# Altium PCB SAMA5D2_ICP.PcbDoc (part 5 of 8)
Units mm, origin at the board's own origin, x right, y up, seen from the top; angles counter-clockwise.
Board outline 150 x 100 mm, 6 copper layers (L1 - TOP, L2 - GND, L3 - SIG, L4 - SIG, L5 - VCC, L6 - BOT), stack 1.512 mm thick; 708 components, 597 nets, 2710 pads, 1437 vias.
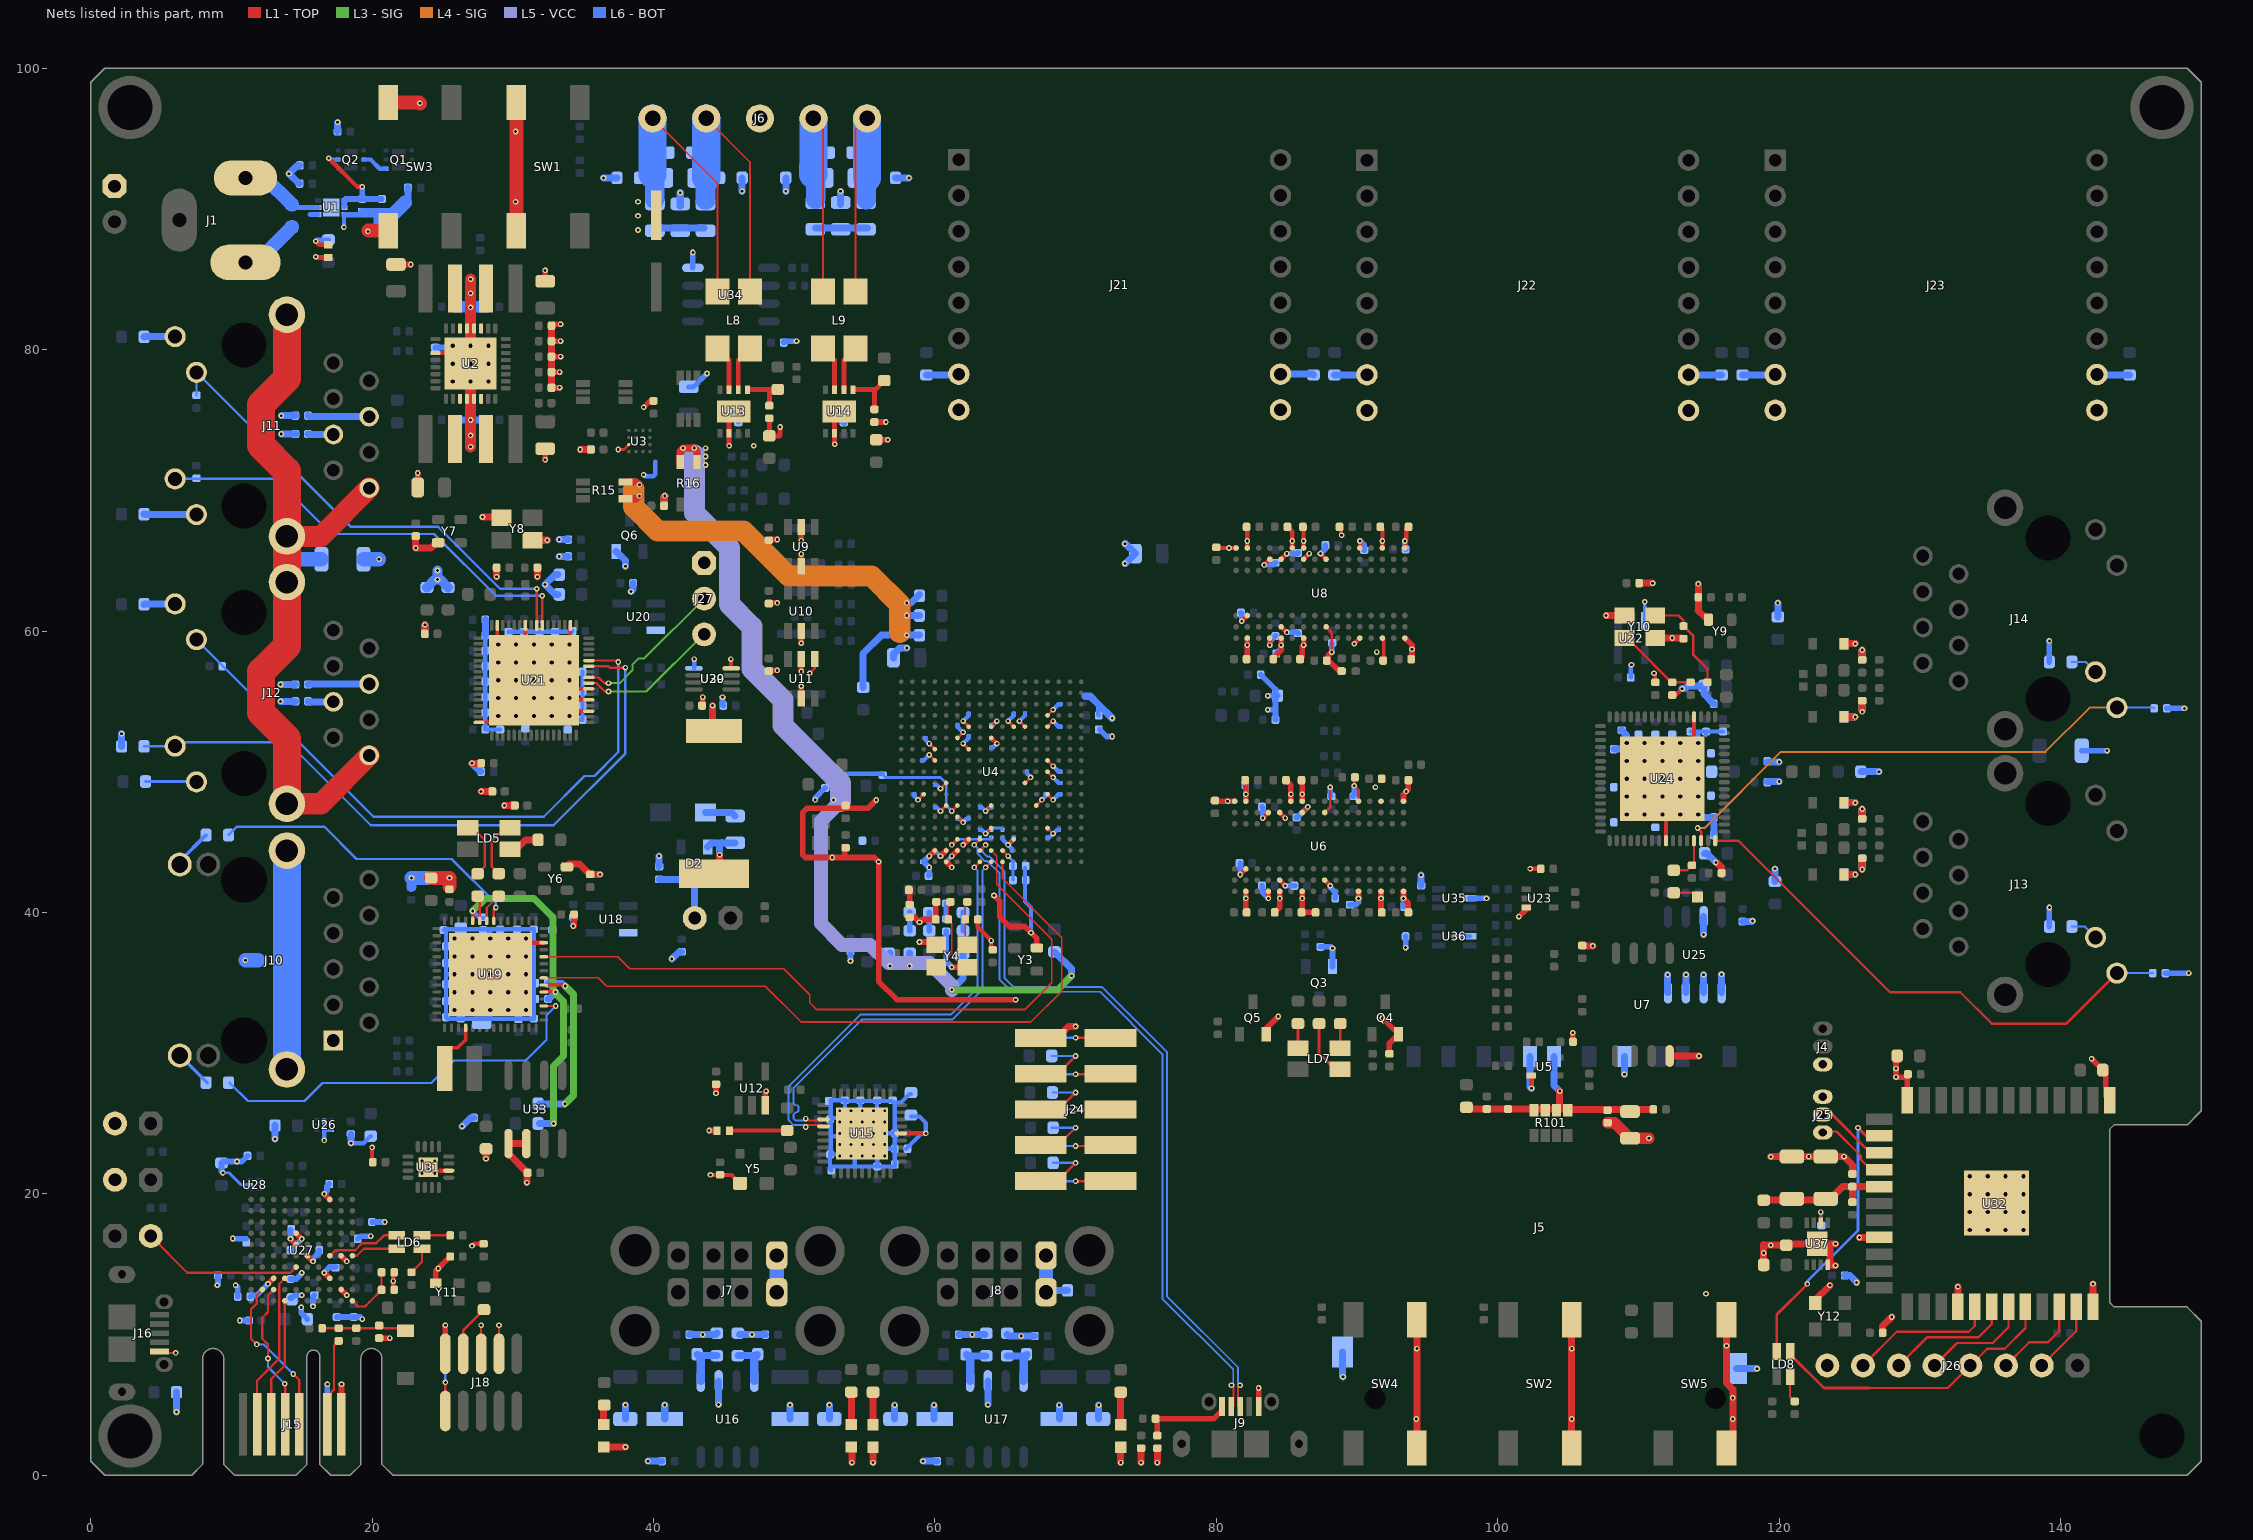
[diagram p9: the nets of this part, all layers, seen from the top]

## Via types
v1: diameter 0.4, hole 0.2, L1 - TOP to L6 - BOT, tented both sides, 1312 vias
v2: diameter 0.55, hole 0.3, L1 - TOP to L6 - BOT, 84 vias
v3: diameter 0.4, hole 0.2, L1 - TOP to L6 - BOT, tented top, 25 vias
v4: diameter 0.55, hole 0.3, L1 - TOP to L6 - BOT, tented bottom, 16 vias

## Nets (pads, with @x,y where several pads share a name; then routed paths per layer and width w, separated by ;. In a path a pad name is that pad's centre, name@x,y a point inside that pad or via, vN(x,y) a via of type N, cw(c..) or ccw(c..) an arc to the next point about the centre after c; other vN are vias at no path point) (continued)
GND: C1.1 C2.1 C3.1 C4.1 C5.2 C6.1 C7.1 C8.1 C9.1 C10.1 C11.1 C12.2 C13.1 C14.2 C15.1 C16.2 C17.1 C18.2 C19.1 C20.1 C21.1 C22.1 C23.1 C24.1 C26.1 C27.1 C28.1 C29.1 C30.1 C31.1 C32.1 C33.1 C34.1 C35.1 C36.1 C37.1 C38.1 C39.1 C40.1 C41.1 C42.1 C43.1 C44.1 C45.1 C46.1 C47.1 C48.1 C49.1 C50.1 C51.1 C52.1 C53.1 C54.1 C55.1 C56.1 C57.1 C58.1 C59.1 C60.1 C61.1 C62.1 C63.1 C64.1 C65.1 C66.1 C67.1 C68.2 C70.1 C72.1 C73.1 C75.1 C76.1 C77.1 C78.1 C79.1 C80.1 C81.1 C82.1 C83.1 C84.1 C85.1 C86.1 C87.1 C88.1 C89.1 C90.1 C91.1 C92.1 C93.1 C94.1 C95.1 C96.1 C97.1 C98.1 C99.1 C100.1 C101.1 C102.1 C103.1 C104.1 C105.1 C106.1 C107.1 C108.1 C109.1 C110.1 C111.1 C112.1 C113.1 C114.1 C115.1 C116.1 C117.1 C118.1 C119.1 C120.1 C121.1 C122.1 C123.1 C124.1 C125.1 C126.1 C127.1 C128.1 C129.1 C130.1 C131.1 C132.1 C133.1 C134.1 C135.1 C136.2 C137.2 C138.2 C139.2 C142.1 C143.1 C144.2 C145.2 C146.1 C147.1 C148.1 C149.1 C150.1 C151.1 C152.1 C153.1 C154.1 C155.1 C156.1 C157.1 C158.1 C159.1 C160.1 C161.1 C162.1 C163.1 C164.1 C165.1 C166.1 C167.2 C168.1 C169.1 C170.1 C171.1 C172.1 C173.1 C174.1 C175.1 C176.1 C177.1 C178.1 C179.1 C180.1 C181.1 C182.1 C183.1 C184.1 C185.1 C186.1 C187.1 C188.1 C189.1 C190.1 C191.1 C192.1 C193.1 C194.1 C195.1 C196.1 C197.1 C198.1 C199.1 C200.1 C201.1 C202.1 C203.1 C204.1 C205.1 C206.1 C207.1 C208.1 C209.1 C210.1 C211.1 C212.1 C213.2 C214.2 C215.2 C216.2 C217.1 C218.1 C219.1 C220.1 C221.1 C222.1 C223.1 C224.1 C225.1 C226.1 C227.1 C228.1 C229.1 C230.1 C231.1 C232.1 C233.1 C234.1 C235.1 C236.1 C237.1 C238.1 C239.1 C240.1 C241.1 C242.1 C244.1 C245.1 C246.1 C247.1 C248.1 C249.1 C250.1 C251.1 C252.1 C253.1 C254.1 C255.1 C256.1 C257.1 C258.1 C259.1 C260.1 C261.1 C262.1 C263.1 C264.1 C265.1 C266.1 C267.1 C268.1 C269.1 C270.1 C271.1 C272.1 C273.1 C274.1 C275.1 C276.1 C277.1 C278.2 C279.2 C280.1 C281.1 C282.1 C283.1 C284.1 C285.1 C286.1 C287.1 C288.1 C289.1 C290.2 C291.1 C292.1 C293.1 C294.1 C295.1 C296.1 C297.1 C298.1 C299.1 C300.2 C301.2 C302.1 C303.2 C304.1 C305.1 D3.2 D4.2 D11.1 D12.1 D13.1 D14.1 D15.1 D16.1 D17.1 D18.1 FB14.1 FB21.1 FB26.2 J1.2 J3.1 J4.3 J5.3 J5.6 J5.12 J6.3 J7.4 J7.8 J8.4 J8.8 J9.5 J10.1 J15.2 J15.3 J16.5 J18.3 J18.5 J18.9 J19.2 J20.2 J21.8 J21.9 J22.8 J22.9 J23.8 J23.9 J24.10 J25.3 J26.8 J27.1 LD1.2 LD2.2 LD3.2 LD4.2 Q3.2 Q4.2 Q5.2 Q6.2 R5.1 R8.1 R10.1 R11.2 R12.1 R13.2 R22.1 R26.1 R64.1 R66.2 R67.1 R76.1 R77.1 R79.2 R82.1 R85.1 R87.1 R92.1 R95.1 R111.1 R112.2 R120.2 R121.2 R122.2 R123.2 R129.1 R133.2 R136.1 R139.1 R149.1 R155.2 R157.2 R162.1 R164.1 R174.2 R175.1 R180.2 R181.2 R198.1 R206.1 R208.1 R216.1 R242.1 R243.1 R248.2 R259.2 R261.1 R262.1 R266.2 R267.2 R268.2 R271.1 SW1.3 SW1.4 SW2.3 SW2.4 SW3.3 SW3.4 SW4.3 SW4.4 SW5.3 SW5.4 U1.2 U1.6 U2.3 U2.12 U2.13 U2.28 U2.29 U2.33 U3.B4 U4.D14 U4.E7 U4.E9 U4.E11 U4.E12 U4.E14 U4.F6 U4.F9 U4.G4 U4.G7 U4.H4 U4.H14 U4.J14 U4.K5 U4.K12 U4.L3 U4.L14 U4.M5 U4.M9 U4.M13 U4.N6 U4.P14 U4.R7 U4.R11 U4.T4 U4.T5 U4.T6 U4.U5 U5.3 U6.A9 U6.B1 U6.B3 U6.B9 U6.D1 U6.D8 U6.E1 U6.E2 U6.E8 U6.F9 U6.G1 U6.G8 U6.G9 U6.J2 U6.J8 U6.M1 U6.M9 U6.P1 U6.P9 U6.T1 U6.T9 U7.4 U8.A9 U8.B1 U8.B3 U8.B9 U8.D1 U8.D8 U8.E1 U8.E2 U8.E8 U8.F9 U8.G1 U8.G8 U8.G9 U8.J2 U8.J8 U8.M1 U8.M9 U8.P1 U8.P9 U8.T1 U8.T9 U9.2 U9.5 U10.2 U11.2 U11.4 U11.5 U12.3 U13.2 U13.9 U14.2 U14.9 U15.37 U16.6 U17.6 U18.3 U19.40 U19.57 U20.3 U21.16 U21.35 U21.37 U21.39 U21.50 U21.58 U21.63 U21.65 U22.3 U23.3 U24.4 U24.41 U24.65 U25.1 U25.2 U25.3 U25.4 U25.7 U26.3 U26.7 U27.B2 U27.C3 U27.E2 U27.E5 U27.F6 U27.G6 U27.K3 U28.5 U29.4 U30.4 U31.6 U31.17 U32.1 U32.13 U32.21 U32.28 U32.36 U32.37 U33.5 U33.6 U34.4 U35.2 U36.2 U37.4 U37.9 Y3.2 Y4.2 Y4.4 Y5.2 Y6.2 Y7.2 Y8.2 Y8.4 Y9.2 Y10.2 Y10.4 Y11.2 Y12.2 | length 656.8
  L1 - TOP w0.15: J16.5@4.85,8.7 v1(6.05,8.7) ; U31.17@24,22.5 U31.17@24.25,22.25 ; J18.5@27.75,8.632 v1(27.75,10.664) ; J18.3@29.02,8.632 v1(29.02,10.664)
  L1 - TOP w0.2: v1(37.5,72.9) 37.9,72.9 U3.B4@38.25,73.25 ; v1(51.1,57) 51.125,57 51.45,57.325 U11.4@51.45,58 ; v1(58.8,48) U4.L3@59.2,48.4 ; v1(59.6,51.2) U4.H4@60,50.8 ; v1(59.6,52) U4.G4@60,51.6 ; v1(60.4,47.2) U4.M5@60.8,47.6 ; v1(60.4,48.8) U4.K5@60.8,49.2 ; U4.N6@61.6,46.8 v1(62,46.4) ; U4.F6@61.6,52.4 v1(62,52.8) ; v1(62,52) U4.G7@62.4,51.6 ; v1(62,53.6) U4.E7@62.4,53.2 ; v1(63.6,47.2) U4.M9@64,47.6 ; U4.E9@64,53.2 v1(64.4,53.6) ; v1(65.2,44.8) U4.R11@65.6,45.2 ; v1(65.2,53.6) U4.E11@65.6,53.2 ; v1(66,53.6) U4.E12@66.4,53.2 ; U4.K12@66.4,49.2 v1(66.8,49.6) ; U4.M13@67.2,47.6 v1(67.6,48) ; U4.P14@68,46 v1(68.4,45.6) ; U4.L14@68,48.4 v1(68.4,48) ; U4.J14@68,50 v1(68.4,49.6) ; U4.H14@68,50.8 v1(68.4,50.4) ; U4.E14@68,53.2 v1(68.4,53.6) ; U4.D14@68,54 v1(68.4,54.4) ; U6.J8@87.7,47.1 88.1,47.5 v1(88.1,48.9) ; U8.J2@87.8,60.3 88.2,59.9 v1(88.2,58.5) ; R85.1@89.85,49.6 89.8,49.55 v1(89.8,49) 90.1,48.7 U6.M9@90.1,47.9 ; U8.P1@91.8,59.5 U8.P1@91.85,59.45 ; U32.1@143.3,26.855 U32.1@143.5,26.655
  L1 - TOP w0.25: U21.16@27.6,53.5 U21.65@28.5,53.5 ; U21.65@28.9,59.1 U21.63@28.9,60.4 ; U21.65@30.9,57.1 U21.58@30.9,60.4 ; U21.65@32.1,55.9 U21.39@35.4,55.9 ; U21.65@32.9,55.1 U21.37@35.4,55.1 ; U21.65@33.7,54.3 U21.35@35.4,54.3 ; U21.65@34.1,59.1 U21.50@34.1,60.4 ; C96.1@91.9,57.9 U8.P1@91.9,59.45 ; v1(111.1,57) 111.2,56.9 R175.1@111.2,56.35 R175.1@111.2,56.25
  L1 - TOP w0.3: v1(20,23.3) 20,22.3 C276.1@20.05,22.25 ; R206.1@21.575,13.175 21.5,13.25 v1(21.5,13.8) 21.5,14.35 C255.1@21.575,14.425 ; U31.17@24.25,21.65 U31.6@25.45,21.65 ; U2.3@24.5,79.75 26.25,79.75 v2(27,79) ; v1(27.1,16.3) 27.25,16.45 R208.1@27.925,16.45 ; v2(29.67,36.87) 30.65,37.85 U19.40@32.2,37.85 ; v1(44.05,21.35) C122.1@44.73,21.35 45.555,21.35 Y5.2@46.155,20.75 ; v1(45.5,58) 45.5,57.375 U30.4@45.525,57.35 ; C60.1@63.05,39.5 63.05,38.95 v1(64,38) 64,37.45 C52.1@64.1,37.35 ; U4.F9@64,52.4 v1(64.4,52) ; C82.1@80,65.95 80.05,65.9 v1(80.9,65.9) U8.A9@81.4,65.9 ; v1(81.7,42.7) U6.B3@82.1,43.1 ; v1(81.8,60.7) U8.B3@82.2,61.1 ; C76.1@82.15,67.4 82.2,67.35 v1(82.2,66.4) U8.B9@82.2,65.9 ; v1(83.3,46.7) U6.D8@83.7,47.1 ; v1(83.4,64.7) U8.D8@83.8,65.1 ; U6.E2@84.5,42.3 v1(84.9,41.9) ; U6.E8@84.5,47.1 v1(84.9,46.7) ; U8.E2@84.6,60.3 v1(85,59.9) ; U8.E8@84.6,65.1 v1(85,65.5) ; C77.1@85.05,67.4 85.4,67.05 v1(85.4,66.4) U8.F9@85.4,65.9 ; U6.G8@86.1,47.1 v1(86.5,47.5) ; C79.1@86.15,67.4 86.2,67.35 v1(86.2,66.4) U8.G9@86.2,65.9 ; U8.G8@86.2,65.1 v1(86.6,65.5) ; v1(87.4,65.5) U8.J8@87.8,65.1 ; U6.J2@87.7,42.3 v1(88.1,41.9) ; v1@88.85,66.8 R92.1@88.85,67.4 ; v1(89.8,59.1) U8.M1@90.2,59.5 ; U8.M9@90.25,65.9 v1@90.25,66.4 ; C80.1@91.65,67.4 91.8,67.25 v1(91.8,66.4) U8.P9@91.8,65.9 ; U8.T9@93.4,65.9 v1(93.4,66.4) 93.5,66.5 93.5,67.25 C81.1@93.65,67.4 ; v2(111.7,49.5) 111.95,49.25 U24.41@111.95,45.1 ; C229.1@112.4,55.45 112.65,55.45 v1(113.1,55.9) ; U24.65@113.95,52.04 U24.4@113.95,53.9
  L1 - TOP w0.305: v1(102.3,43.1) C221.1@103.05,43.1 ; U5.3@102.375,28.4 102.375,27.525 v1(102.4,27.5)
  L1 - TOP w0.35: v1(16,86.6) 16.05,86.55 D3.2@16.9,86.55 ; v1(39.3,75.9) 39.75,76.35 R22.1@40,76.35 ; v1(45.375,73.169) U13.2@45.375,74.05 45.375,75.275 v1(45.7,75.6) ; C129.1@48.231,75.119 C124.1@48.231,73.869 48.969,73.869 49,73.9 v1(49,74.5) ; v1@52.875,73.369 U14.2@52.875,74.05 52.875,75.275 v1(53.2,75.6)
  L1 - TOP w0.4: v1(14.2,16.8) U27.F6@14.6,16.4 ; U27.G6@14.6,17.2 v1(15,16.8) ; U27.E5@15.4,15.6 v1(15.8,15.2) ; v1(16.6,14.4) U27.C3@17,14 ; v1(16.6,20) U27.K3@17,19.6 ; U27.B2@17.8,13.2 v1(18.2,12.8) ; U27.E2@17.8,15.6 v1(18.2,15.2) ; J15.2@17.825,3.625 v1(17.825,6.475) ; C251.1@20.5,9.75 v1(21.25,9.75) ; C18.2@21.7,86.05 v1(22.75,86.05) ; C12.2@23.25,70.2 v1(23.25,71.225) ; Y11.2@24.525,13.825 24.525,14.525 C250.1@25.55,15.55 ; J18.9@25.21,8.632 v1(25.21,10.664) ; v1(32.3,72.175) C14.2@32.3,72.95 ; C16.2@32.3,84.85 v1(32.3,85.625) ; R8.1@32.75,77.3 v1(33.325,77.3) ; C9.1@32.75,78.4 v1(33.325,78.4) ; C8.1@32.75,79.5 v1(33.4,79.5) ; C10.1@32.75,80.6 v1(33.4,80.6) ; C2.1@32.75,81.7 32.85,81.8 v1(33.4,81.8) ; v1@34.35,39.033 R133.2@34.35,39.855 ; C274.1@43.45,54.7 43.5,54.75 v1(43.5,55.3) ; v1(43.95,24.5) D4.2@44.5,24.5 ; v1(44.445,27.145) C123.1@44.445,27.795 ; U12.3@47.945,26.3 47.945,27.245 v1(48,27.3) ; C98.1@48.2,57.15 48.25,57.2 v1(48.8,57.2) ; C109.1@48.2,61.95 48.25,62 v1(48.8,62) ; C92.1@48.2,66.45 48.25,66.5 v1(48.8,66.5) ; U11.2@50.5,55.2 v1(50.5,56.075) ; v1(50.5,57.125) U11.5@50.5,58 ; v1(50.5,59.125) U10.2@50.5,60 ; U9.2@50.5,64.6 v1(50.5,65.475) ; v1(50.5,66.425) U9.5@50.5,67.3 ; C51.1@53.65,44.6 53.6,44.55 53.6,43.9 ; C130.1@55.7,74.85 v1(56.512,74.85) ; v1(55.83,47.993) 55.238,47.4 50.9,47.4 50.6,47.1 50.6,44.1 50.8,43.9 v1(52.7,43.9) 53.6,43.9 ; C125.1@55.831,73.594 v1(56.643,73.594) ; R76.1@58.2,39.65 58.611,39.65 58.611,39.589 v1(58.9,39.3) 59.1,39.5 C67.1@60.05,39.5 60.05,40.7 R5.1@60.1,40.75 ; v1(58.9,37.9) 59.9,37.9 Y4.2@60.1,37.7 ; v1(59.6,44) U4.T4@60,44.4 ; v1(60.4,44) U4.T5@60.8,44.4 ; U4.U5@60.8,43.6 v1(61.2,43.2) ; v1(61.2,36.1) Y4.4@62.3,36.1 ; v1(61.2,44) U4.T6@61.6,44.4 ; v1(62,44.8) U4.R7@62.4,45.2 ; v1(64.2,41.2) 64.6,40.8 64.6,39.7 65.3,39 66.387,39 v1(66.825,38.562) 67.246,38.141 Y3.2@67.246,37.477 ; v1(65.735,33.8) 57.3,33.8 56,35.1 v1(56,43.6) 55.7,43.9 53.6,43.9 ; C106.1@79.9,47.95 79.95,47.9 v1(80.8,47.9) U6.A9@81.3,47.9 ; C101.1@82.05,49.4 82.1,49.35 v1(82.1,48.4) U6.B9@82.1,47.9 ; U6.B1@82.1,41.5 v1(82.1,41) 82.1,40.05 C115.1@82.15,40 ; C93.1@82.15,58 82.2,58.05 v1(82.2,59) U8.B1@82.2,59.5 ; J9.5@83,4.9 v1(83,6.2) ; Q5.2@83.55,31.35 83.55,31.75 v1(84.4,32.6) ; v1(83.7,41) U6.D1@83.7,41.5 ; v1(83.8,59) U8.D1@83.8,59.5 ; C94.1@84.05,58 84.05,58.075 84.6,58.625 v1(84.6,59) U8.E1@84.6,59.5 ; C117.1@84.15,40 84.5,40.35 v1(84.5,41) U6.E1@84.5,41.5 ; C102.1@84.95,49.4 85.3,49.05 v1(85.3,48.4) U6.F9@85.3,47.9 ; C95.1@85.95,58 86.1,58.15 86.1,58.9 v1(86.2,59) U8.G1@86.2,59.5 ; C103.1@86.05,49.4 86.1,49.35 v1(86.1,48.4) U6.G9@86.1,47.9 ; U6.G1@86.1,41.5 v1(86.1,41) 86.1,40.05 C118.1@86.05,40 R87.1@87.05,40 ; v1(88.2,58.5) 87.954,58.254 87.954,58.004 C294.1@87.85,57.9 87.981,57.9 88.731,57.15 R95.1@88.9,57.15 ; v1(90.1,41) U6.M1@90.1,41.5 ; U6.P1@91.7,41.5 v1(91.7,41) 91.7,40.05 C120.1@91.75,40 ; v1(91.8,32.5) Q4.2@92.95,31.35 92.3,30.7 R243.1@92.3,29.95 ; U6.T1@93.3,41.5 v1(93.3,41) 93.65,40.65 C121.1@93.65,40 ; U6.T9@93.3,47.907 U6.T9@93.3,47.9 93.3,48.4 v1(93.5,48.6) 93.65,48.75 C105.1@93.65,49.4 ; U8.T1@93.5,59.4 93.9,59 v1(93.9,58.7) 93.9,58.05 C97.1@93.85,58 ; v1(101.5,39.7) 102.02,40.22 U23.3@102.02,40.35 ; v1(105.325,31.45) 105.325,30.825 C78.1@105.35,30.8 ; C302.1@128.385,29.8 128.3,29.715 v1(128.3,28.9) v1(128.3,28.3) C301.2@128.95,28.3 ; U32.13@129.1,26.655 129.1,28.45 C301.2@129.15,28.5 ; v1(142.2,29.6) R248.2@143,28.8 ; R248.2@143.2,28.9 143.2,26.955 U32.1@143.3,26.855
  L1 - TOP w0.5: C182.1@23.1,66.75 v1(23.1,65.9) 24.2,65.9 24.575,66.275 Y7.2@24.7,66.275 ; C192.1@23.75,59.8 v1(23.75,60.45) ; v1(27.1,50.6) R266.2@27.75,50.6 ; v1(27.75,48.6) R155.2@28.55,48.6 ; v1(27.85,68.1) Y8.4@28.7,68.1 ; v1(28.1,22.5) C160.1@28.1,23.2 ; v1(28.85,63.85) C183.1@28.85,64.5 ; v1(29.4,47.6) R267.2@30.15,47.6 ; U33.6@30.965,23.575 U33.5@29.695,23.575 29.695,22.855 C167.2@31.05,21.5 31,21.45 v1(31,20.8) ; Y8.2@31.6,66.45 v1(32.45,66.45) ; v1(31.75,63.85) C189.1@31.75,64.5 ; R8.1@32.75,77.3 C9.1@32.75,78.4 C8.1@32.75,79.5 C10.1@32.75,80.6 C2.1@32.75,81.7 ; Y6.2@34,43.455 34.75,43.455 C155.1@35.5,42.705 v1(36.195,42.705) ; v1(34.8,72.9) C22.1@35.55,72.9 ; LD3.2@36.46,2.01 v1(38.01,2.01) ; C21.1@40.75,68.9 40.75,69.55 v1(40.8,69.6) ; v1(44.2,54.7) 44.2,53 C5.2@44.3,52.9 ; v1(54.1,0.9) LD4.2@54.1,2 ; v1(55.6,0.9) LD1.2@55.6,2 ; J24.10@67.52,31.08 68.68,31.08 69.5,31.9 v1(70,31.9) ; v1(73.2,0.9) LD2.2@73.2,2 ; v1(74.652,0.9) R129.1@74.652,1.924 ; v1(75.802,0.9) C152.1@75.802,1.924 ; SW4.3@94.25,1.95 v1(94.25,9) SW4.4@94.25,11.05 ; SW2.3@105.25,1.95 v1(105.25,4) v1(105.25,9) SW2.4@105.25,11.05 ; C85.1@106,37.65 106.025,37.625 v1(106.75,37.625) ; v1(107.7,61.1) Y10.2@109,61.1 ; C218.1@110.05,63.4 v1(111,63.4) ; Y10.4@111.2,59.5 v1(112.4,59.5) 113.1,59.5 113.2,59.4 C222.1@113.2,59.45 ; U7.4@112.21,29.8 v1(114.3,29.8) ; v1(114.25,63.35) C224.1@114.25,62.4 114.25,61.491 114.229,61.471 Y9.2@114.75,60.95 ; v1@115.55,43.55 115.561,43.55 115.9,43.211 C228.1@115.9,42.8 ; SW5.3@116.25,1.95 116.7,2.4 v1(116.7,4) v1(116.7,5.5) 116.7,6.1 116.25,6.55 v1(116.25,9.2) SW5.4@116.25,11.05 ; C303.2@118.9,14.95 v1(118.9,15.8) 118.9,16.4 118.95,16.35 v1(119.4,16.35) C305.1@120.5,16.35 120.6,16.45 U37.9@122.7,16.45 123.6,16.45 ; v1(119.4,22.639) 119.411,22.65 C300.2@120.902,22.65 v1(122.101,22.65) C279.2@123.3,22.65 v1(124.6,22.65) 125.2,22.05 C278.2@125.2,21.415 ; Y12.2@122.55,12.25 122.55,12.45 v1(123.6,13.5) ; v1(124,14.9) 123.75,14.9 123.6,15.05 123.6,16.45 ; v1(124,16.45) 123.6,16.45 ; D14.1@124.615,42.7 v1(125.4,42.7) ; D13.1@124.615,47.8 v1(125.4,47.8) ; D17.1@124.615,53.9 v1(125.4,53.9) ; D18.1@124.615,59.1 v1(125.4,59.1) ; v1(125.7,16.9) 127.105,16.9 U32.21@127.12,16.915 ; v1(125.9,43.05) C246.1@125.9,43.75 ; C244.1@125.9,46.65 v1(125.9,47.35) ; v1@125.9,54.35 C165.1@125.9,55.05 ; C166.1@125.9,57.95 v1(125.9,58.65) ; C277.1@127.35,10.125 127.35,10.6 v1(128,11.25) ; U32.28@132.7,11.975 v1(132.7,13.4) ; U32.36@142.3,11.975 v1(142.3,13.6)
  L1 - TOP w0.8: v1(27,73.1) v1(27,73.9) v1(27,75) v2(27,77.73) U2.33@27,77.8 ; U2.33@27,80.2 v2(27,80.27) v1(27,83) v1(27,84) v1(27,85) ; C119.1@107.8,25.05 108.3,25.05 C116.1@109.4,23.95 v1(110.75,23.95)
  L1 - TOP w1: v1@19.75,88.45 SW3.4@21.15,88.45 ; SW3.3@21.15,97.55 23.35,97.55 v1(23.4,97.5) ; C159.1@24.2,42.455 v1(25.5,42.455) R139.1@25.5,41.855 ; SW1.4@30.25,88.45 SW1.3@30.25,97.55
  L6 - BOT w0.15: C264.1@14.2,17.45 C264.1@14.25,17.5
  L6 - BOT w0.2: v1(9.4,21.5) 9.828,21.5 10.678,20.65 U28.5@11.3,20.65 ; U26.7@16.6,24.5 U26.3@17.125,24.5
  L6 - BOT w0.25: U22.3@110.45,60.7 v1(110.45,62.075)
  L6 - BOT w0.3: v1(16.6,23.8) 16.6,24.5 U26.7@16.6,24.9 ; v1(18,88.7) 18,89.575 U1.6@18.025,89.6 ; v1(18.5,23.6) 19.4,23.6 C253.1@19.9,24.1 ; C6.1@20.5,89.6 C6.1@20.7,89.8 ; v2(27.13,35.6) v2(25.86,35.6) 25.25,35.6 ; C195.1@28.05,53 C203.1@29.1,53 ; C195.1@28.05,53.1 C200.1@28.05,54.2 C196.1@28.05,55.3 C197.1@28.05,56.4 C198.1@28.05,57.5 C194.1@28.05,58.6 C199.1@28.05,59.7 ; 28.4,32.6 v2(28.4,33.06) v2(28.4,34.33) ; v2(28.4,36.87) v2(28.4,38.14) 28.4,38.8 ; v2(29.67,35.6) v2(30.94,35.6) 31.475,35.6 31.5,35.575 ; C201.1@29.7,59.95 C212.1@30.8,59.95 C202.1@31.9,59.95 34.2,59.95 C204.1@34.25,60 ; v2(34.04,53.96) 34.3,53.7 C207.1@34.95,53.7 C208.1@34.95,54.7 C206.1@34.95,55.7 C209.1@34.95,57.1 ; v1(39.3,71.1) 39.4,71 40,71 40.131,71.131 40.131,72.05 ; U29.4@42.875,57.35 42.9,57.35 v1(42.9,58) ; v1(45.7,75.6) 46.025,75.275 C131.1@46.025,74.819 ; C128.1@52.6,25.4 52.6,26.65 R122.2@53.6,26.65 R122.2@53.6,26.6 ; C126.1@52.63,21.675 52.55,21.755 R112.2@52.55,22.8 R112.2@52.6,22.8 ; C128.1@52.63,25.2 52.6,25.17 R112.2@52.6,22.8 ; C128.1@52.63,25.35 52.63,25.4 53.13,25.4 ; C126.1@52.7,21.95 C134.1@55.9,21.95 ; 52.7,24.1 53.23,24.1 ; v3@53.13,22.8 R112.2@52.6,22.8 ; 53.6,25.97 R122.2@53.6,26.6 ; 54.3,22.1 54.3,22.63 ; v3@54.7,25.97 R121.2@54.7,26.6 ; 55.88,26 C127.1@55.88,26.6 ; 55.9,22.58 C134.1@55.9,21.95 ; v3@56.5,24.3 C133.1@57.15,24.3 ; 56.52,23.2 57.03,23.2 57.15,23.32 C133.1@57.15,24.3 ; R120.2@57.03,26.5 56.93,26.6 C127.1@55.88,26.6 ; C135.1@57.05,23.2 C135.1@57.15,23.2 R111.1@57.15,22.1 57.15,21.95 C134.1@55.9,21.95 ; C146.1@58.3,27.1 58.2,27.1 57.6,26.5 57.15,26.5 C133.1@57.15,24.3 ; C34.1@58.538,48.4 58.538,48.263 v1(58.8,48) ; C53.1@59.062,50.8 59.2,50.8 v1(59.6,51.2) ; C73.1@59.338,52.4 59.338,52.262 v1(59.6,52) ; C70.1@60,44.262 60.138,44.263 v1(60.4,44) ; C39.1@60,47.462 60.138,47.463 v1(60.4,47.2) ; C31.1@60,49.062 60.138,49.063 v1(60.4,48.8) ; C72.1@60.938,43.6 60.938,43.738 v1(61.2,44) ; C65.1@61.6,46.663 61.737,46.663 v1(62,46.4) 62.262,46.662 C64.1@62.4,46.663 ; C41.1@61.6,53.338 61.6,53.2 v1(62,52.8) ; v1(62,52) 62.4,52.4 C37.1@62.4,52.538 ; v1(62,53.6) 62.4,54 C48.1@62.4,54.138 ; C56.1@63.2,47.462 63.338,47.462 v1(63.6,47.2) 63.862,47.462 C35.1@64,47.462 ; C38.1@64,51.738 64.138,51.738 v1(64.4,52) ; C42.1@64,53.338 64.138,53.338 v1(64.4,53.6) ; R79.2@64.8,45.338 64.8,45.2 v1(65.2,44.8) ; v1(65.2,53.6) 65.6,54 C36.1@65.6,54.138 ; C66.1@65.6,45.338 65.6,45.2 v1(65.2,44.8) ; v1(66,53.6) 66.4,54 C40.1@66.4,54.138 ; R67.1@66.4,43.15 66.4,40.775 66.825,40.35 v1(66.825,38.562) ; C44.1@66.538,50 66.538,49.862 v1(66.8,49.6) ; v1(67.6,48) 67.862,48.262 C55.1@67.862,48.4 ; C50.1@68,45.338 68.137,45.338 v1(68.4,45.6) 68.662,45.862 C46.1@68.8,45.862 ; v1(68.4,48) 68.8,48.4 C33.1@68.937,48.4 ; v1(68.4,49.6) 68.8,49.2 C43.1@68.937,49.2 ; v1(68.4,50.4) 68.8,50 C45.1@68.938,50 ; v1(68.4,53.6) 68.8,53.2 C54.1@68.937,53.2 ; v1(68.4,54.4) 68.8,54.8 C49.1@68.938,54.8 ; 71.6,54.8 71.6,54.05 R64.1@71.65,54 ; v1(96.9,38.3) U36.2@98,38.3 ; C239.1@113.7,52.85 114.2,52.85 ; v2(114.24,52.04) 114.24,52.81 114.2,52.85 ; C225.1@114.8,52.6 C225.1@114.8,52.85 ; C233.1@116,52.85 C225.1@114.8,52.85 ; 25.25,35.6 C170.1@25.25,36.4 C168.1@25.25,37.6 25.25,38.6 C247.1@25.1,38.75 25.15,38.8 28.4,38.8 ; 25.25,35.6 C172.1@25.25,34.9 C175.1@25.25,33.7 C176.1@25.25,32.555 25.355,32.45 C280.1@26.3,32.45 C180.1@31.5,32.45 31.5,35.575 ; 28.4,38.8 C179.1@29.1,38.8 C171.1@30.3,38.8 C161.1@31.5,38.8 31.5,35.575 ; R122.2@53.6,26.6 R121.2@54.7,26.6 ; R121.2@54.7,26.6 C127.1@55.88,26.6 ; v1(65.2,44.8) C47.1@65.462,44.538 ; C47.1@65.462,44.538 C47.1@65.462,44.4 C47.1@65.462,44.538 ; 114.2,52.85 C225.1@114.8,52.85
  L6 - BOT w0.305: C217.1@109.45,56.7 109.45,57.55 v1(109.5,57.6)
  L6 - BOT w0.35: C1.1@14.5,90.1 U1.2@16.175,90.1 ; C29.1@42.5,77.35 42.85,77.35 v1(43.8,78.3)
  L6 - BOT w0.4: v1(9,13.5) 9.05,13.55 C265.1@9.05,14.2 ; v1(9.4,21.5) 9.3,21.6 R216.1@9.3,22.2 9.4,22.3 v1(10.4,22.3) 10.75,22.3 C273.1@11.15,22.7 ; v1(10.1,16.825) 10.125,16.8 C270.1@11.05,16.8 ; v1(10.3,13.5) 10.45,13.35 C254.1@10.45,12.7 ; v1(10.6,11) C267.1@11.25,11 ; C258.1@14.2,12.6 14.3,12.6 14.5,12.8 v1(15,12.8) ; C269.1@14.2,13.95 14.611,13.95 15,14.339 v1(15,14.4) ; C268.1@14.2,16 v1(15,16.8) ; v1(14.2,16.8) C264.1@14.2,17.45 ; C1.1@14.3,90.3 C1.1@14.5,90.1 ; v1(14.965,11.935) 14.965,11.535 C263.1@15.4,11.1 ; v1(15.8,12) 15.8,12.7 C260.1@15.9,12.8 ; v1(15.8,15.2) 15.8,15.4 16.25,15.85 C259.1@16.25,16 ; v1(16.6,14.4) 16.6,14.411 16.989,14.8 C266.1@17.4,14.8 ; v1(16.6,20) 16.8,20.2 16.8,20.55 C271.1@16.95,20.7 ; J15.3@16.825,3.625 v1(16.825,6.475) ; C261.1@17.5,11.25 C262.1@18.7,11.25 19.15,11.25 v1(19.3,11.1) ; U1.6@18.05,89.575 C6.1@20.525,89.575 ; C257.1@18.975,16.8 19.175,17 v1(19.9,17) ; C272.1@20,18 v1(20.9,18) ; C3.1@24.5,80.15 25.61,80.15 v2(25.73,80.27) ; R10.1@32.75,77.3 v1(33.325,77.3) ; v1(34.3,39.033) C156.1@34.3,39.55 ; U34.4@42.8,85.805 v1(42.8,86.9) ; v1(44.9,55.3) 44.9,54.75 C275.1@44.95,54.7 ; C241.1@49.25,80.5 49.25,80.525 49.325,80.6 v1(50.162,80.6) ; v1(51.5,48) 51.5,48.15 C68.2@52.2,48.85 ; v1(54,36.55) C62.1@54,37.25 ; v1(58.9,37.9) 60.6,37.9 60.8,37.7 ; C57.1@59.55,42.6 59.6,42.65 v1(59.6,43.2) 59.2,43.6 v1(59.6,44) ; R77.1@60.8,38.65 60.8,37.7 ; v1(61.2,36.1) 60.8,36.5 60.8,37.7 ; C28.1@71.7,53 72.2,52.5 v1(72.6,52.5) ; v1(81.7,42.7) C111.1@81.7,43.5 ; C88.1@81.75,61.3 81.8,61.25 v1@81.8,60.8 ; C99.1@82.05,49 82.1,48.95 v1(82.1,48.4) ; C23.1@83.15,56.9 84.2,55.85 R26.1@84.2,55.4 ; C112.1@83.25,41.9 83.25,41.45 v1(83.7,41) ; C107.1@83.25,47.5 83.3,47.45 v1(83.3,46.7) ; v1(83.4,64.7) 84.05,64.7 C83.1@84.2,64.85 ; v1(83.65,54.4) 84.2,54.4 ; v1(83.65,55.4) R26.1@84.2,55.4 ; v1(83.8,59) 83.8,59.25 C89.1@84.2,59.65 ; C26.1@84.2,53.7 84.2,54.4 ; R26.1@84.2,55.3 84.2,54.4 ; C87.1@84.25,58.4 84.6,58.75 v1(84.6,59) ; R26.1@84.35,55.4 R26.1@84.2,55.4 ; v1(84.9,41.9) C113.1@85.55,41.9 ; v1(85,59.9) 85.75,59.9 C90.1@85.8,59.85 ; v1(85,65.5) 85.75,65.5 C84.1@85.8,65.55 ; C108.1@85.7,46.75 85.75,46.75 v1(86.5,47.5) ; R242.1@87.4,37.55 88.15,37.55 v1(88.25,37.45) Q3.2@88.25,36.15 ; v1(87.4,65.5) 87.75,65.85 C86.1@87.75,66.1 ; v1(88.1,41.9) 88.1,41.761 88.45,41.411 C292.1@88.45,41 ; C110.1@88.1,48.25 v1(88.1,48.9) ; v1(88.2,58.5) C91.1@88.2,59.15 ; C114.1@89.5,40.55 89.911,40.55 90.1,40.739 v1(90.1,41) ; C291.1@89.7,48.25 89.8,48.35 v1(89.8,49) ; v1(90.2,66.4) 90.236,66.4 90.5,66.136 C293.1@90.5,65.75 ; v1(93.3,41) 93.3,40.45 C100.1@93.35,40.4 ; v1(93.4,66.4) 93.4,65.85 C75.1@93.45,65.8 ; v1(93.45,37.5) C59.1@93.45,38.3 ; U35.2@97.996,41 v1(99.2,41) ; R164.1@139.2,39 v1(139.2,40.35) ; R82.1@139.2,57.8 v1(139.2,59.3) ; R198.1@141.5,51.5 v1(143.3,51.5) ; R261.1@147.45,35.69 v1(149.1,35.69) ; R262.1@147.55,54.5 v1(148.8,54.5)
  L6 - BOT w0.5: R136.1@2.2,51.8 v1(2.2,52.7) ; v1(6.1,4.5) FB26.2@6.1,5.9 ; v1(13.1,23.9) C252.1@13.1,24.85 C252.1@13.1,24.9 ; v1(13.5,55) C216.2@14.55,55 ; v1(13.5,56.2) C215.2@14.55,56.2 ; v1(13.55,74) C214.2@14.55,74 C214.2@14.6,74 ; v1(13.55,75.3) C213.2@14.55,75.3 C213.2@14.6,75.3 ; C4.1@14.85,91.8 14.8,91.8 v1(14.1,92.5) 14.685,93.085 R11.2@14.854,93.085 ; R13.2@17.55,95.5 v1(17.55,96.15) ; v1(18.5,23.6) C256.1@18.5,24.25 ; R12.1@19.3,89.8 C6.1@20.6,89.8 ; C6.1@20.7,89.8 21.7,89.8 ; 22.35,90.45 22.55,90.65 C19.1@22.55,91.5 ; C190.1@23.75,59.8 v1(23.75,60.45) ; C11.1@25.85,75 v1(27,75) C13.1@28.15,75 ; v1(26.4,24.8) 27,25.4 C249.1@27.25,25.4 ; v1(27.1,50.6) 27.7,50 R157.2@27.75,50 ; C199.1@28.05,59.7 R149.1@28.05,60.8 ; v1(29.4,47.6) R259.2@30.05,47.6 R259.2@30.15,47.6 ; C186.1@33.2,62.6 33,62.6 v1(32.3,63.3) 33,64 C188.1@33.2,64 ; v1(33.3,65.3) C193.1@33.95,65.3 ; v1(33.3,66.5) C191.1@33.95,66.5 ; v1(34.8,72.9) C24.1@35.55,72.9 ; v1(36.45,92.2) C136.2@37.4,92.2 ; Q6.2@37.35,65.65 38,65 v1(38,64.6) ; C284.1@38,4 v1(38,5) ; v1(38.4,62.8) 38.55,62.95 C184.1@38.55,63.4 ; v1(39.6,1) C144.2@40.6,1 ; C7.1@40.4,43.25 v1(40.4,44) ; C20.1@40.75,68.9 40.75,69.55 v1(40.8,69.6) ; C282.1@40.8,4 v1(40.8,5) ; v1(41.3,36.7) 41.8,37.2 R268.2@42,37.2 ; C142.1@41.9,90.2 v1(41.9,91.15) ; C148.1@42.55,10 v1(43.5,10) 44.4,10 C151.1@44.5,10.1 ; v1(44.625,5.025) U16.6@44.625,6.71 ; C147.1@46.1,10 v1(47,10) C153.1@47.95,10 ; v1(46.3,91.25) C137.2@46.3,92.2 ; v1(49.4,91.25) C138.2@49.4,92.2 ; C295.1@49.7,4 v1(49.7,5) ; C297.1@52.5,4 v1(52.5,5) ; v1(53.2,75.6) 53.2,75.144 C132.1@53.525,74.819 ; C143.1@53.3,90.3 v1(53.3,91.25) ; C32.1@57.05,58.1 57.05,58.35 57.5,58.8 v1(58,58.8) ; C285.1@57.14,3.99 v1(57.14,4.99) ; C139.2@57.2,92.2 v1(58.15,92.2) ; v1(59.15,1) C145.2@60.15,1 ; C283.1@59.94,3.99 v1(59.94,4.99) ; C149.1@61.7,10 v1(62.65,10) C281.1@63.55,10 ; v1(63.765,5.015) U17.6@63.765,6.7 ; C150.1@65.14,9.99 65.24,9.89 v1(66.14,9.89) C154.1@67.09,9.89 ; J8.8@67.9,13.01 68.033,13.143 FB14.1@69.423,13.143 ; C296.1@68.84,3.99 v1(68.84,4.99) ; C27.1@70.65,55.362 71.038,55.362 71.6,54.8 v1(72.6,53.8) ; C298.1@71.64,3.99 v1(71.64,4.99) ; v1(73.5,64.8) 73.55,64.8 C30.1@74.25,65.5 73.55,66.2 v1(73.5,66.2) ; J5.12@88.975,8.775 88.975,7.025 v1(89,7) ; C58.1@94.55,41.9 v1(94.55,42.65) ; J5.3@102.3,29.775 102.3,27.6 v1(102.4,27.5) ; C230.1@108.25,51.6 108.72,51.6 v2(109.16,52.04) 109.16,52.59 C223.1@108.8,52.95 ; v1@109,28.5 J5.6@109,29.775 ; v1(112.075,35.575) 112.075,34.32 U25.4@112.095,34.3 ; v1(113.1,55.9) 113.3,55.9 113.5,56.1 C226.1@114.65,56.1 114.65,55.525 C231.1@115.35,54.825 ; U25.3@113.365,34.3 113.375,34.31 v1(113.375,35.575) ; v2(114.24,46.96) 114.45,46.75 C234.1@115.35,46.75 ; v1(114.625,35.575) 114.625,34.31 U25.2@114.635,34.3 ; v1(114.625,38.425) U25.7@114.625,39.72 ; C227.1@114.7,44.2 114.85,44.2 v1(115.5,43.55) ; C232.1@115.35,45.5 115.35,46.3 ; v1(115.9,35.6) 115.9,34.305 U25.1@115.905,34.3 ; J5.12@116.975,7.575 v1(118.425,7.575) ; C235.1@117.45,39.4 C235.1@117.4,39.35 118.05,39.35 v1(118.1,39.4) ; C289.1@119.15,49.3 v1(120,49.3) ; C288.1@119.15,50.7 v1(120,50.7) ; C248.1@119.7,42.2 v1(119.7,43.1) ; C181.1@119.9,61 v1(119.9,62) ; D12.1@124.615,42.7 v1(125.4,42.7) ; D11.1@124.615,47.8 v1(125.4,47.8) ; D15.1@124.615,53.9 v1(125.4,53.9) ; D16.1@124.615,59.1 v1(125.4,59.1) ; R271.1@124.65,14.2 125.037,14.2 125.5,13.737 v1(125.5,13.7) ; C236.1@125.8,50 v1(127.1,50) ; v1@125.9,43.15 C242.1@125.9,43.85 ; C240.1@125.9,46.65 v1(125.9,47.35) ; v1@125.9,54.35 C162.1@125.9,55.05 ; C164.1@125.9,57.95 v1(125.9,58.65)
  L6 - BOT w0.7: C245.1@22.779,41.805 22.8,41.827 v1(22.8,42.455) ; C185.1@23.9,63.1 24.45,63.65 v1(24.65,63.65) ; v1(24.65,64.3) v1(24.65,63.65) ; C187.1@25.4,63.1 24.85,63.65 v1(24.65,63.65)
  L6 - BOT w0.8: C17.1@25.85,83.05 C15.1@28.15,83.05 ; v1@27,83.125 v1(27,84) v1@27,84.875
  L6 - BOT w1: v1(11,36.6) FB21.1@11.9,36.6 ; J1.2@11,92.2 12.4,92.2 C1.1@14.3,90.3 ; R162.1@19.4,65.1 v1(20.5,65.1) ; 20.6,88.5 20.6,89.4 ; 20.95,89.05 21.7,89.8 22.35,90.45 ; v1(22.8,42.455) C157.1@24.2,42.455 ; J7.4@48.76,15.63 J7.8@48.76,13.01 J7.8@48.893,13.143 ; J8.8@67.9,13.01 J8.4@67.9,15.62
  other v1: 94.2,4 114.8,12.9 24.7,14.7 23.55,21.45 24.45,21.45 24,21.9 23.55,22.35 24.45,22.35 109,28.5 91.3,48.9 125.9,54.25 91.4,58.5 88.9,66.8 47.125,73.169 52.875,73.269 19.7,88.4 38.9,88.5 38.9,89.5 30.2,90.5 38.9,90.5 30.2,95.5
  other v2: 25.86,33.06 27.13,33.06 29.67,33.06 30.94,33.06 25.86,34.33 27.13,34.33 29.67,34.33 30.94,34.33 28.4,35.6 25.86,36.87 27.13,36.87 30.94,36.87 25.86,38.14 27.13,38.14 29.67,38.14 30.94,38.14 109.16,46.96 110.43,46.96 111.7,46.96 112.97,46.96 109.16,48.23 110.43,48.23 111.7,48.23 112.97,48.23 114.24,48.23 109.16,49.5 110.43,49.5 112.97,49.5 114.24,49.5 109.16,50.77 110.43,50.77 111.7,50.77 112.97,50.77 114.24,50.77 110.43,52.04 111.7,52.04 112.97,52.04 28.96,53.96 30.23,53.96 31.5,53.96 32.77,53.96 28.96,55.23 30.23,55.23 31.5,55.23 32.77,55.23 34.04,55.23 28.96,56.5 30.23,56.5 31.5,56.5 32.77,56.5 34.04,56.5 28.96,57.77 30.23,57.77 31.5,57.77 32.77,57.77 34.04,57.77 28.96,59.04 30.23,59.04 31.5,59.04 32.77,59.04 34.04,59.04 25.73,77.73 28.27,77.73 25.73,79 28.27,79 28.27,80.27
  other v3: 53.23,22.7 54.03,22.7 54.83,22.7 55.63,22.7 56.43,22.7 53.23,23.5 54.03,23.5 54.83,23.5 55.63,23.5 56.43,23.5 53.23,24.3 54.03,24.3 54.83,24.3 55.63,24.3 56.43,24.3 53.23,25.1 54.03,25.1 54.83,25.1 55.63,25.1 56.43,25.1 53.23,25.9 54.03,25.9 54.83,25.9 55.63,25.9 56.43,25.9
  other v4: 133.545,17.44 134.815,17.44 136.085,17.44 137.355,17.44 133.545,18.71 134.815,18.71 136.085,18.71 137.355,18.71 133.545,19.98 134.815,19.98 136.085,19.98 137.355,19.98 133.545,21.25 134.815,21.25 136.085,21.25 137.355,21.25
"GND ETH": J11.8 J11.13 J11.14 J12.8 J12.13 J12.14 R162.2 | length 58.1
  L1 - TOP w1.5: J12.14@13.95,47.725 16.36,47.725 J12.8@19.79,51.155 ; J11.14@13.95,66.725 16.36,66.725 J11.8@19.79,70.155
  L1 - TOP w2: J12.14@13.95,47.725 13.95,52.35 12.1,54.2 12.1,57.1 13.95,58.95 J12.13@13.95,63.475 J11.14@13.95,66.725 13.95,71.35 12.1,73.2 12.1,76.1 13.95,77.95 J11.13@13.95,82.475
  L6 - BOT w0.5: 13.95,65.2 14.05,65.1
  L6 - BOT w1: 14.05,65.1 R162.2@16.4,65.1
  L6 - BOT w2: J12.13@13.95,63.475 13.95,65.2 J11.14@13.95,66.725
"GND ETH3": FB21.2 J10.0 | length 15.6
  L6 - BOT w2: J10.0@13.95,28.854 J10.0@13.95,44.404
GNDUTMII: C74.1 R78.1 R79.1 U4.P9 | length 2.5
  L1 - TOP w0.2: v1(63.6,45.6) U4.P9@64,46
  L6 - BOT w0.2: v1@63.731,45.731 64,46 64.662,46 R79.1@64.8,45.862
  L6 - BOT w0.3: R78.1@63.2,45.862 63.338,45.863 v1(63.6,45.6) v1@63.731,45.731
GPIO0: J13.9 R261.2 U24.48 | length 38
  L1 - TOP w0.165: U24.48@115.45,45.1 117.1,45.1 127.87,34.33 132.87,34.33 135.1,32.1 140.41,32.1 J13.9@144,35.69
  L6 - BOT w0.165: J13.9@144,35.69 R261.2@146.55,35.69
GPIO1: J14.9 R262.2 U24.46 | length 37
  L1 - TOP w0.165: v1(114.2,46) 114.45,45.75 U24.46@114.45,45.1
  L4 - SIG w0.14: v1(114.2,46) 114.7,46 120.113,51.413 138.913,51.413 142.06,54.56 J14.9@144,54.56
  L6 - BOT w0.14: J14.9@144,54.56 146.59,54.56 R262.2@146.65,54.5
GPIO20: J26.4 LD8.2 U32.32 | length 21.2
  L1 - TOP w0.165: 126.4,6.2 131.98,6.2 J26.4@133.58,7.8 134.78,9 136.025,9 137.5,10.475 U32.32@137.5,11.975
  L1 - TOP w0.2: LD8.2@120.775,8.8 120.775,8.605 123.18,6.2 126.4,6.2
GPOI2: R172.2 R173.2 U24.45 | length 3.3
  L1 - TOP w0.165: R173.2@112.5,43 113.45,43 R172.2@113.8,43.35 113.95,43.5 U24.45@113.95,45.1
HHSA_n: J9.2 U4.R8 | length 52.2
  L1 - TOP w0.135: J9.2@81.05,4.9 81.206,4.9 81.206,6.294 81.099,6.401 v1(81.075,6.401)
  L1 - TOP w0.165: v1(62.8,44.8) U4.R8@63.2,45.2
  L6 - BOT w0.135: v1(62.8,44.8) 63.031,44.569 63.031,44.169 63.55,43.65 63.725,43.65 64.6,42.775 64.6,35.222 65.46,34.362 71.738,34.362 76.162,29.938 76.162,12.56 81.2,7.522 81.2,6.5 81.101,6.401 v1(81.075,6.401)
HHSA_p: J9.3 U4.T8 | length 52.2
  L1 - TOP w0.135: J9.3@81.7,4.9 81.544,4.9 81.544,6.309 81.635,6.4 v1@81.7,6.4
  L1 - TOP w0.165: U4.T8@63.2,44.4 v1(63.6,44.8)
  L6 - BOT w0.135: v1(63.6,44.8) 63.369,44.569 63.369,44.309 63.69,43.988 63.865,43.988 64.938,42.915 64.938,35.362 65.6,34.7 71.878,34.7 76.5,30.078 76.5,12.7 81.538,7.662 81.538,6.499 81.636,6.4 v1@81.7,6.4
  other v1: 81.687,6.402
HHSB_n: U4.U9 U15.30 | length 30.7
  L1 - TOP w0.135: v1(50.825,25.35) 50.825,25.248 50.854,25.219 51.999,25.219 U15.30@52.08,25.3
  L1 - TOP w0.165: v1(63.6,43.2) U4.U9@64,43.6
  L6 - BOT w0.135: v1(50.825,25.35) 50.825,25.247 50.8,25.222 50.089,25.222 49.936,25.375 49.936,25.636 50.1,25.8 50.2,25.8 50.3,25.9 50.3,26.2 50.2,26.3 50.089,26.3 49.936,26.452 49.936,27.508 54.831,32.403 61.252,32.403 63.369,34.519 63.369,42.969 v1(63.6,43.2)
HHSB_p: U4.U8 U15.31 | length 30.8
  L1 - TOP w0.135: v1(50.825,24.75) 50.825,24.841 50.865,24.881 51.999,24.881 U15.31@52.08,24.8
  L1 - TOP w0.165: v1(62.8,43.2) U4.U8@63.2,43.6
  L6 - BOT w0.135: v1(50.825,24.75) 50.825,24.842 50.782,24.884 49.949,24.884 49.599,25.235 49.599,27.648 54.691,32.741 61.112,32.741 63.031,34.659 63.031,42.969 v1(62.8,43.2)
HSIC_DATA: U4.T9 U19.38 | length 49.9
  L1 - TOP w0.125: U19.38@32.2,36.85 37.45,36.85 38.308,35.992 49.267,35.992 51.1,34.159 51.1,33.6 51.604,33.096 66.396,33.096 68.295,34.995 68.295,38.104 64.4,41.999 64.4,44 U4.T9@64,44.4
HSIC_STROBE: U4.U10 U19.35 | length 49.9
  L1 - TOP w0.125: U19.35@32.2,35.35 36.075,35.35 36.678,34.747 47.953,34.747 50.49,32.21 66.805,32.21 69.005,34.41 69.005,38.212 64.8,42.417 U4.U10@64.8,43.6
LED0: R144.1 U19.31 | length 28.4
  L1 - TOP w0.165: U19.31@32.2,33.35 v1(33.05,33.35)
  L6 - BOT w0.165: R144.1@9.874,27.9 11.174,26.6 15.2,26.6 16.476,27.876 24.201,27.876 25.8,29.475 30.917,29.475 32.4,30.958 32.4,32.7 v1(33.05,33.35)
LED1: R145.1 U19.49 | length 22.8
  L1 - TOP w0.165: U19.49@28.65,39.4 28.65,40.2 v1(28.8,40.35)
  L6 - BOT w0.165: R145.1@9.8,45.5 10.4,46.1 16.6,46.1 18.9,43.8 25.65,43.8 28.8,40.65 v1(28.8,40.35)
LED1_0: J11.11 R263.1 U21.55 | length 31.6
  L1 - TOP w0.165: U21.55@32.1,60.4 v1(32.1,62.5)
  L6 - BOT w0.165: J11.11@6,70.815 13.178,70.815 17.093,66.9 24.4,66.9 28.8,62.5 v1(32.1,62.5)
LED1_1: J11.10 R264.1 U21.56 | length 34.8
  L1 - TOP w0.165: U21.56@31.7,60.4 v1(31.7,63)
  L6 - BOT w0.165: R264.1@7.52,76.75 J11.10@7.52,78.385 18.505,67.4 24.7,67.4 29.1,63 v1(31.7,63)
LED1_3U: LD6.2 U27.E3 | length 5.2
  L1 - TOP w0.165: U27.E3@17,15.6 17.4,16 18.8,16 19.3,16.5 20.3,16.5 20.85,17.05 LD6.2@21.6,17.05
LED2: R137.1 U19.50 | length 2.1
  L1 - TOP w0.165: U19.50@28.15,39.4 28.15,40.336 28.969,41.155 R137.1@29,41.155
LED2_0: J12.11 R136.2 U21.43 | length 47.6
  L1 - TOP w0.165: U21.43@35.4,57.5 36.8,57.5 36.9,57.4 v1(38,57.4)
  L6 - BOT w0.165: 14,52.1 19.9,46.2 32.9,46.2 38,51.3 v1(38,57.4)
  L6 - BOT w0.2: R136.2@3.8,51.8 3.815,51.815 J12.11@6,51.815 6.285,52.1 14,52.1
LED2_1: J12.10 R265.2 U21.44 | length 45.6
  L1 - TOP w0.165: U21.44@35.4,57.9 37.4,57.9 v1(37.5,57.8)
  L6 - BOT w0.165: J12.10@7.52,59.385 20.105,46.8 32.2,46.8 35.1,49.7 35.8,49.7 37.5,51.4 v1(37.5,57.8)
LED2_3U: LD6.3 U27.E1 | length 3.4
  L1 - TOP w0.165: U27.E1@18.6,15.6 18.904,15.6 19.404,16.1 LD6.3@21.75,16.1
LED3: R138.1 U19.51 | length 1.8
  L1 - TOP w0.165: R138.1@27.5,41.155 27.65,41.005 U19.51@27.65,39.4
NetC1_2: C1.2 J1.1 U1.1 U1.7 | length 4.9
  L6 - BOT w0.35: 15.6,89.6 U1.1@16.175,89.6
  L6 - BOT w1: J1.1@11,86.2 11.8,86.2 C1.2@14.3,88.7
NetC5_1: C5.1 D2.2 R3.2 | length 4.5
  L1 - TOP w0.508: C5.1@44.3,42.75 44.8,43.25 44.7,43.35 v1(44.7,44.1)
  L6 - BOT w0.5: D2.2@43.85,44.65 44.15,44.95 44.85,44.95 ; 44.9,44.95 R3.2@45.8,44.95
  L6 - BOT w0.508: v1(44.7,44.1) 44.7,44.8 44.85,44.95
NetC6_2: C6.2 Q1.1 Q2.2 Q2.5 R12.2 U1.4 U1.5 | length 9.8
  L1 - TOP w0.3: v1(16.925,93.6) 18.958,91.567 v1(19.304,91.567)
  L6 - BOT w0.3: v1(16.925,93.6) 17.025,93.5 Q2.2@17.587,93.5 ; Q2.5@19.413,93.5 19.9,93.5 20.55,92.85 Q1.1@20.987,92.85
  L6 - BOT w0.4: U1.5@18.025,90.2 U1.4@18.025,90.6 18.125,90.7 R12.2@19.3,90.7 ; v1(19.304,91.567) 19.3,91.563 R12.2@19.3,90.7 ; C6.2@20.7,90.7 R12.2@19.3,90.7
NetC7_2: C7.2 D2.3 J2.2 | length 5.3
  L6 - BOT w0.5: C7.2@40.4,42.35 D2.3@42.9,42.35 42.93,42.32 J2.2@42.93,39.6
NetC60_2: C60.2 R70.1 Y4.1 | length 3.2
  L1 - TOP w0.125: Y4.1@62.3,37.7 62.15,37.85 C60.2@62.15,39.5 62.15,40.6 R70.1@62.3,40.75
NetC63_2: C63.2 R67.2 U4.T10 | length 2.4
  L1 - TOP w0.2: U4.T10@64.8,44.4 v1(65.2,44)
  L6 - BOT w0.2: v1(65.2,44) 65.55,43.65 R67.2@65.55,43.3 C63.2@65.55,42.3
NetC67_2: C67.2 R71.1 Y4.3 | length 5.3
  L1 - TOP w0.125: Y4.3@60.1,36.1 60.2,36.1 61.2,37.1 61.2,39.25 C67.2@60.95,39.5 60.95,40.6 R71.1@61.1,40.75
NetC68_1: C68.1 R68.2 U4.M6 | length 11.6
  L1 - TOP w0.2: v1(61.2,47.2) U4.M6@61.6,47.6
  L6 - BOT w0.2: R68.2@56.3,49.85 56.344,49.776 56.45,49.6 60.4,49.6 60.8,49.2 60.8,47.6 v1(61.2,47.2)
  L6 - BOT w0.3: C68.1@52.2,49.85 R68.2@56.3,49.85
NetC69_1: C69.1 R76.2 | length 1.1
  L1 - TOP w0.4: C69.1@58.15,41.6 58.2,41.55 R76.2@58.2,40.55
NetC71_1: C71.1 R77.2 | length 1.1
  L6 - BOT w0.4: R77.2@60.8,39.55 C71.1@60.8,40.65
NetC74_2: C74.2 R78.2 U4.R6 | length 3.6
  L1 - TOP w0.2: v1(61.2,44.8) U4.R6@61.6,45.2
  L6 - BOT w0.2: v1(61.2,44.8) 61.6,45.2 63.862,45.2 C74.2@64,45.338
NetC116_2: C116.2 C119.2 J5.4 R101.1 R101.2 R101.3 R101.4 R102.2 R103.2 R104.2 R106.2 | length 17.3
  L1 - TOP w0.5: R106.2@97.775,26.15 97.9,26.025 R104.2@99.225,26.025 R103.2@100.725,26.025 103.375,26.025 R101.2@104.175,26.025 ; v1(104.4,27.3) 104.4,26.25 R101.2@104.175,26.025 ; R101.1@104.95,25.975 104.975,26 R101.1@105,26 ; R102.2@111,26 107.8,26 R101.1@105,26 ; R101.2@104.175,26.025 104.975,26.025 R101.1@105,26
  L6 - BOT w0.5: J5.4@104,29.775 104,27.7 v1@104.388,27.312
NetC129_2: C129.2 R109.1 U13.5 | length 3.4
  L1 - TOP w0.35: U13.5@46.675,77.15 48.2,77.15 ; C129.2@48.231,76.019 48.231,77.15 R109.1@49,77.15
NetC130_2: C130.2 R110.1 U14.5 | length 3.9
  L1 - TOP w0.35: U14.5@54.175,77.15 55.7,77.15 ; C130.2@55.7,75.75 55.7,77.15 ; R110.1@56.4,77.8 55.75,77.15 55.7,77.15
NetC135_2: C135.2 C146.2 U15.14 | length 5.6
  L1 - TOP w0.3: U15.14@57.58,24.3 v1(59.355,24.3)
  L6 - BOT w0.3: C135.2@57.95,23.2 59.05,24.3 v1(59.355,24.3) 59.355,25.045 58.9,25.5 C146.2@58.3,25.5
NetC136_1: C136.1 C140.2 J6.1 L8.L1 R114.2 R116.2 | length 19.7
  L1 - TOP w0.125: J6.1@39.939,96.431 44.55,91.82 L8.L1@44.55,84.125
  L6 - BOT w1.4: R116.2@40.099,90.7 40.099,92.2
  L6 - BOT w2: 39.925,92.45 39.939,94 J6.1@39.939,96.431
NetC137_1: C137.1 C140.1 J6.2 L8.L2 R114.1 R117.1 | length 19.5
  L1 - TOP w0.125: J6.2@43.749,96.431 46.85,93.33 L8.L2@46.85,84.125
  L6 - BOT w1.4: R117.1@43.699,90.65 43.699,92.3
  L6 - BOT w2: 43.749,92.2 J6.2@43.749,96.431
NetC138_1: C138.1 C141.2 J6.4 L9.L1 R115.2 R118.2 | length 18.1
  L1 - TOP w0.125: J6.4@51.369,96.431 52.05,95.75 L9.L1@52.05,84.125
  L6 - BOT w1.4: R118.2@51.529,90.7 51.529,92.2
  L6 - BOT w2: C138.1@51.355,92.45 51.369,94 J6.4@51.369,96.431
NetC139_1: C139.1 C141.1 J6.5 L9.L2 R115.1 R119.1 | length 18.5
  L1 - TOP w0.125: L9.L2@54.35,84.125 54.35,95.602 J6.5@55.179,96.431
  L6 - BOT w1.4: R119.1@55.129,90.65 55.129,92.3
  L6 - BOT w2: 55.179,92.2 J6.5@55.179,96.431
NetC142_2: C142.2 R116.1 R117.2 | length 3.3
  L6 - BOT w0.5: R116.1@40.3,88.65 41.9,88.65 R117.2@43.6,88.65
NetC143_2: C143.2 R118.1 R119.2 | length 3.7
  L6 - BOT w0.5: R118.1@51.5,88.65 53.3,88.65 R119.2@55.2,88.65
NetC147_2: C147.2 FB10.1 U16.8 | length 3.3
  L6 - BOT w0.5: C147.2@46,8.5 47.3,8.5 FB10.1@47.4,8.6
  L6 - BOT w0.6: U16.8@47.165,6.71 47.165,8.365 FB10.1@47.3,8.5
NetC150_2: C150.2 FB12.1 U17.8 | length 3.3
  L6 - BOT w0.5: C150.2@65.14,8.49 66.44,8.49 FB12.1@66.54,8.59
  L6 - BOT w0.6: U17.8@66.305,6.7 66.305,8.355 FB12.1@66.44,8.49
NetC151_2: C151.2 FB11.1 U16.5 | length 3.3
  L6 - BOT w0.5: FB11.1@43.1,8.6 43.2,8.5 C151.2@44.5,8.5
  L6 - BOT w0.6: FB11.1@43.2,8.5 43.355,8.345 U16.5@43.355,6.71
NetC152_2: C152.2 J9.1 R130.2 | length 6.5
  L1 - TOP w0.4: C152.2@75.802,2.824 75.802,3.899 R130.2@75.677,4.024 79.824,4.024 80.4,4.6 J9.1@80.4,4.9
NetC174_2: C174.2 FB20.2 U19.34 | length 13.5
  L1 - TOP w0.25: U19.34@32.2,34.85 33.65,34.85 v1(33.725,34.775)
  L3 - SIG w0.5: v1(33.7,26.4) 34.3,27 34.3,34.2 v1(33.725,34.775)
  L6 - BOT w0.4: C174.2@32.5,34.975 32.525,35 33.5,35 v1(33.725,34.775)
  L6 - BOT w0.5: FB20.2@31.9,26.4 v1(33.7,26.4)
NetC177_2: C177.2 C178.2 FB18.2 U19.33 U19.52 | length 26.1
  L1 - TOP w0.25: U19.52@27.15,39.4 v1(27.15,40.105) ; U19.33@32.2,34.35 v1(33.025,34.35)
  L3 - SIG w0.5: v1(27.15,40.105) 28.045,41 31.5,41 32.85,39.65 32.85,34.525 v1(33.025,34.35) 33.025,34.25 33.6,33.675 33.6,29.8 32.9,29.1 v1(32.9,25)
  L6 - BOT w0.3: v1(27.15,40.105) 27.655,39.6 C177.2@27.9,39.6
  L6 - BOT w0.5: FB18.2@31.9,25 v1(32.9,25) ; C178.2@32.5,33.85 32.575,33.85 33.025,34.3 v1(33.025,34.35)
NetC213_1: C213.1 J11.4 | length 4.4
  L6 - BOT w0.5: C213.1@15.45,75.3 15.515,75.235 J11.4@19.79,75.235
NetC214_1: C214.1 J11.5 | length 1.8
  L6 - BOT w0.5: C214.1@15.45,74 15.485,73.965 J11.5@17.25,73.965
NetC215_1: C215.1 J12.4 | length 4.4
  L6 - BOT w0.5: C215.1@15.45,56.2 15.485,56.235 J12.4@19.79,56.235
NetC216_1: C216.1 J12.5 | length 1.8
  L6 - BOT w0.5: C216.1@15.45,55 15.485,54.965 J12.5@17.25,54.965
NetC222_2: C222.2 R169.1 Y10.1 | length 7.2
  L1 - TOP w0.165: Y10.1@111.2,61.1 112.85,61.1 113.2,60.75 C222.2@113.2,60.35 113.9,59.65 113.9,58.3 114.9,57.3 R169.1@114.9,56.35
NetC229_2: C229.2 R170.1 Y10.3 | length 5.3
  L1 - TOP w0.165: Y10.3@109.5,59.1 109.6,59.1 112.35,56.35 C229.2@112.4,56.35 R170.1@113.7,56.35
NetC251_2: C251.2 D10.1 R199.1 R200.1 R201.2 | length 6
  L1 - TOP w0.165: R200.1@16.45,10.45 R201.2@17.625,10.45 R199.1@18.875,10.45 22.2,10.45 D10.1@22.375,10.275
NetC254_2: C254.2 U27.C8 | length 2.2
  L1 - TOP w0.4: v1(12.6,13.6) U27.C8@13,14
  L6 - BOT w0.4: C254.2@11.35,12.7 11.425,12.775 11.775,12.775 v1(12.6,13.6)
NetC255_2: C255.2 R206.2 U27.A1 | length 4
  L1 - TOP w0.165: U27.A1@18.6,12.4 19,12 19.5,12 19.507,12 19.8,12.293 19.8,12.3 R206.2@20.675,13.175 C255.2@20.675,14.425
NetC278_1: C278.1 C279.1 C300.1 FB27.2 R247.2 U32.18 | length 9.7
  L1 - TOP w0.5: FB27.2@118.9,19.55 123.2,19.55 C279.1@123.3,19.65 123.65,19.65 124.515,20.515 C278.1@125.2,20.515 ; R247.2@125.2,19.415 C278.1@125.2,20.515 ; U32.18@127.12,20.515 C278.1@125.2,20.515
NetC281_2: C281.2 FB13.1 U17.5 | length 3.3
  L6 - BOT w0.5: FB13.1@62.24,8.59 62.34,8.49 C281.2@63.64,8.49
  L6 - BOT w0.6: FB13.1@62.34,8.49 62.495,8.335 U17.5@62.495,6.7
NetC304_2: C304.2 U37.6 | length 1.7
  L1 - TOP w0.165: U37.6@122.95,17.95 v1(122.95,18.7)
  L6 - BOT w0.14: v1(122.95,18.7) 123,18.65 C304.2@123,17.75
NetD1_2: D1.2 R3.1 | length 2.2
  L6 - BOT w0.5: D1.2@43.7,47.1 45.55,47.1 R3.1@45.8,46.85
NetD3_1: D3.1 R14.1 | length 1.9
  L1 - TOP w0.35: v1(16,87.7) 16.25,87.45 D3.1@16.9,87.45
  L6 - BOT w0.35: v1(16,87.7) 16.1,87.8 R14.1@16.9,87.8
NetD4_1: D4.1 R124.2 | length 4.3
  L1 - TOP w0.3: D4.1@45.4,24.5 R124.2@49.5,24.5 R124.2@49.7,24.5
NetD9_2: D9.2 R173.1 | length 1.8
  L1 - TOP w0.165: R173.1@112.5,41.4 113.9,41.4 D9.2@114.2,41.1
NetFB3_1: FB3.1 FB4.1 FB5.1 FB6.1 R15.2 | length 36.2
  L1 - TOP w0.5: R15.2@38,69.4 38.8,69.4 v1(39,69.6) ; R15.2@38,70.6 38.8,70.6 v1(39,70.4)
  L4 - SIG w1.5: 38.6,70.1 38.6,68.8 40.3,67.1 46.4,67.1 49.6,63.9 55.5,63.9 57.5,61.9 57.5,59.9
  L6 - BOT w0.5: FB6.1@54.9,56 54.9,58.4 56.2,59.7 v1(58,59.7) FB5.1@58.9,59.7 ; v1(58,61.1) FB3.1@58.9,61.1 ; v1(58,62) 58.3,62 FB4.1@58.9,62.6
NetFB7_1: FB7.1 FB8.1 FB9.1 R16.2 R20.1 R21.1 | length 69.6
  L1 - TOP w0.5: R16.2@41.9,72 41.9,72.8 v1(42.1,73) v1(42.9,73) 43.1,72.8 R16.2@43.1,72
  L3 - SIG w0.5: v1(61.2,34.5) 68.7,34.5 v1(69.7,35.5)
  L5 - VCC w1: 53.3,47.9 51.9,46.5 51.9,39.2 53.4,37.7 55.4,37.7 56.7,36.4 58.2,36.4 59.6,36.4 61.2,34.8 v1(61.2,34.5)
  L5 - VCC w1.5: 42.9,72.5 42.9,72.4 42.9,68.4 45.4,65.9 45.4,61.9 47,60.3 47,57.3 49.2,55.1 49.2,53.3 53.3,49.2 53.3,47.9
  L6 - BOT w0.5: v1@52.854,48.054 53.5,48.7 FB8.1@53.5,49 ; v1(56.8,36.2) FB7.1@56.8,37.1 ; v1(58.2,36.2) R21.1@58.2,37.1 ; v1(61.2,34.5) 62,35.3 R20.1@62,37.1 ; FB9.1@68.5,37.2 69.7,36 v1(69.7,35.5)
  other v1: 52.8,48 43.7,71.8 43.7,72.4 43.7,73
NetJ10_12: J10.12 R144.2 | length 2.7
  L6 - BOT w0.25: J10.12@6.33,29.844 R144.2@8.274,27.9
NetJ10_14: J10.14 R145.2 | length 2.9
  L6 - BOT w0.25: J10.14@6.33,43.414 6.33,43.63 R145.2@8.2,45.5
NetJ11_9: J11.9 R158.2 | length 2.2
  L6 - BOT w0.5: R158.2@3.8,80.9 3.825,80.925 J11.9@6,80.925
NetJ11_12: J11.12 R159.2 | length 3.7
  L6 - BOT w0.5: R159.2@3.8,68.3 3.825,68.275 J11.12@7.52,68.275
NetJ12_9: J12.9 R160.2 | length 2.2
  L6 - BOT w0.5: R160.2@3.8,61.9 3.825,61.925 J12.9@6,61.925
NetJ12_12: J12.12 R161.1 | length 3.6
  L6 - BOT w0.2: R161.1@3.9,49.3 7.495,49.3 J12.12@7.52,49.275
NetJ13_10: J13.10 R164.2 | length 2
  L6 - BOT w0.165: R164.2@140.8,39 141.71,39 J13.10@142.48,38.23
NetJ14_10: J14.10 R82.2 | length 2
  L6 - BOT w0.165: R82.2@140.8,57.8 141.78,57.8 J14.10@142.48,57.1
NetJ15_4: J15.4 R201.1 | length 4.2
  L1 - TOP w0.165: J15.4@16.887,5.687 17.3,6.1 17.3,9.225 R201.1@17.625,9.55
NetJ15_8: J15.8 U27.B9 | length 11.6
  L1 - TOP w0.165: v1(11.8,9.3) 11.4,9.7 11.4,11.8 11.8,12.2 11.8,12.8 U27.B9@12.2,13.2 ; v1(14.4,7.2) 14.825,6.775 J15.8@14.825,3.625
  L6 - BOT w0.165: v1(11.8,9.3) 12.3,9.3 v1(14.4,7.2)
NetJ15_10: J15.10 U27.B8 | length 10.6
  L1 - TOP w0.165: v1(12.6,8.3) 12.6,9.3 12.2,9.7 12.2,11.2 12.6,11.6 12.6,12.8 U27.B8@13,13.2 ; v1(13.8,6.5) 13.825,6.475 J15.10@13.825,3.625
  L6 - BOT w0.165: v1(12.6,8.3) 12.6,7.7 v1(13.8,6.5)
NetJ15_12: J15.12 U27.A7 | length 9.2
  L1 - TOP w0.165: J15.12@12.825,3.625 12.825,6.825 13.8,7.8 U27.A7@13.8,12.4
NetJ15_14: J15.14 U27.C7 | length 11.2
  L1 - TOP w0.165: J15.14@11.825,3.625 11.825,6.725 13.4,8.3 13.4,13.6 U27.C7@13.8,14
NetJ17_2: J17.2 U27.D6 | length 11.6
  L1 - TOP w0.165: J17.2@4.27,17 6.87,14.4 14.2,14.4 U27.D6@14.6,14.8
NetJ18_7: J18.7 R209.1 | length 3.8
  L1 - TOP w0.165: J18.7@26.47,8.632 26.47,10.295 R209.1@27.95,11.775
NetJ18_10: J18.10 R210.1 | length 4
  L1 - TOP w0.165: J18.10@25.21,4.568 v1(25.21,6.6)
  L6 - BOT w0.165: v1(25.21,6.6) R210.1@25.21,8.55
NetJ21_7: J21.7 R229.2 | length 2.3
  L6 - BOT w0.5: R229.2@59.4,78.2 61.645,78.2 J21.7@61.7,78.255
NetJ21_10: J21.10 R236.2 | length 2.4
  L6 - BOT w0.5: J21.10@84.56,78.255 86.845,78.255 R236.2@86.9,78.2
NetJ22_7: J22.7 R230.2 | length 2.3
  L6 - BOT w0.5: R230.2@88.4,78.2 90.685,78.2 J22.7@90.7,78.215
NetJ22_10: J22.10 R237.2 | length 2.3
  L6 - BOT w0.5: J22.10@113.56,78.215 113.575,78.2 R237.2@115.9,78.2
NetJ23_7: J23.7 R231.2 | length 2.3
  L6 - BOT w0.5: R231.2@117.4,78.2 119.695,78.2 J23.7@119.72,78.225
NetJ23_10: J23.10 R238.2 | length 2.3
  L6 - BOT w0.4: J23.10@142.58,78.225 J23.10@142.605,78.2
  L6 - BOT w0.5: J23.10@142.605,78.2 R238.2@144.9,78.2
NetJ24_1: J24.1 R224.2 | length 4.1
  L1 - TOP w0.165: v1(70,20.9) 72.46,20.9 J24.1@72.48,20.92
  L6 - BOT w0.165: R224.2@68.4,20.9 v1(70,20.9)
NetJ24_2: J24.2 R232.1 | length 4.6
  L1 - TOP w0.165: J24.2@67.52,20.92 68.72,20.92 v1(70,22.2)
  L6 - BOT w0.165: R232.1@68.4,22.2 v1(70,22.2)
NetJ24_3: J24.3 R225.2 | length 4.2
  L1 - TOP w0.165: v1(70,23.4) 72.42,23.4 J24.3@72.48,23.46
  L6 - BOT w0.165: R225.2@68.35,23.4 v1(70,23.4)
NetJ24_4: J24.4 R233.1 | length 4.7
  L1 - TOP w0.165: J24.4@67.52,23.46 68.76,23.46 v1(70,24.7)
  L6 - BOT w0.165: R233.1@68.3,24.7 R233.1@68.4,24.7 v1(70,24.7)
NetJ24_5: J24.5 R226.2 | length 4.1
  L1 - TOP w0.165: v1(70,26) J24.5@72.48,26
  L6 - BOT w0.165: R226.2@68.35,26 v1(70,26)
NetJ24_6: J24.6 R234.1 | length 4.6
  L1 - TOP w0.165: J24.6@67.52,26 68.8,26 v1(70,27.2)
  L6 - BOT w0.165: R234.1@68.35,27.2 v1(70,27.2)
NetJ24_7: J24.7 R227.1 | length 4.1
  L1 - TOP w0.165: v1(70,28.5) 72.44,28.5 J24.7@72.48,28.54
  L6 - BOT w0.165: R227.1@68.35,28.5 v1(70,28.5)
NetJ24_8: J24.8 R235.2 | length 4.7
  L1 - TOP w0.165: J24.8@67.52,28.54 68.74,28.54 v1(70,29.8)
  L6 - BOT w0.165: R235.2@68.3,29.8 v1(70,29.8)
NetJ24_9: J24.9 R228.1 | length 4.2
  L1 - TOP w0.165: v1(70,31.1) 72.46,31.1 J24.9@72.48,31.08
  L6 - BOT w0.165: R228.1@68.3,31.1 v1(70,31.1)
NetJ25_1: J25.1 U32.17 | length 5.3
  L1 - TOP w0.165: J25.1@123.1,24.43 124.072,24.43 125.8,22.702 125.8,22.45 126.535,21.715 U32.17@127.12,21.715
NetJ25_2: J25.2 U32.16 | length 5.2
  L1 - TOP w0.2: J25.2@123.1,25.7 123.7,25.7 126.485,22.915 U32.16@127.12,22.915
NetJ26_2: J26.2 U32.35 | length 5.2
  L1 - TOP w0.165: J26.2@138.66,7.8 141.1,10.24 U32.35@141.1,11.975
NetJ26_3: J26.3 U32.34 | length 6.5
  L1 - TOP w0.165: J26.3@136.12,7.8 137.77,9.45 139.1,9.45 139.9,10.25 U32.34@139.9,11.975
NetJ26_5: J26.5 U32.31 | length 7.8
  L1 - TOP w0.165: J26.5@131.04,7.8 132.64,9.4 135.175,9.4 136.3,10.525 U32.31@136.3,11.975
NetJ26_6: J26.6 U32.30 | length 9
  L1 - TOP w0.165: J26.6@128.5,7.8 130.5,9.8 134.15,9.8 135.1,10.75 U32.30@135.1,11.975
NetJ26_7: J26.7 U32.29 | length 10.5
  L1 - TOP w0.165: J26.7@125.96,7.8 128.36,10.2 133.475,10.2 133.9,10.625 U32.29@133.9,11.975
NetJ27_2: J27.2 U21.41 | length 11.1
  L1 - TOP w0.165: U21.41@35.4,56.7 36.1,56.7 36.5,56.3 v1(36.8,56.3)
  L3 - SIG w0.14: v1(36.8,56.3) 37.6,56.3 38.5,57.2 38.5,57.6 38.95,58.05 39.35,58.05 J27.2@43.6,62.3
NetJ27_3: J27.3 U21.40 | length 10.1
  L1 - TOP w0.165: U21.40@35.4,56.3 35.934,56.3 36.534,55.7 v1(36.8,55.7)
  L3 - SIG w0.14: v1(36.8,55.7) 39.499,55.7 43.559,59.76 J27.3@43.6,59.76
NetL1_1: L1.1 U2.11
NetL2_1: L2.1 U2.14
NetL3_1: L3.1 U2.27
NetL4_1: L4.1 U2.30
NetL5_1: L5.1 R19.2 | length 1.3
  L6 - BOT w0.4: R19.2@59.6,38.7 L5.1@59.6,40
NetL6_1: L6.1 R20.2 | length 1.3
  L6 - BOT w0.4: R20.2@62,38.7 L6.1@62,40
NetL7_1: L7.1 R21.2 | length 1.3
  L6 - BOT w0.4: R21.2@58.2,38.7 L7.1@58.2,40
NetL8_L1': L8.L1' U13.7 | length 3.3
  L1 - TOP w0.35: L8.L1'@44.55,80.075 45.375,79.25 U13.7@45.375,77.15
NetL8_L2': L8.L2' U13.6 | length 3.3
  L1 - TOP w0.35: U13.6@46.025,77.15 46.025,79.25 L8.L2'@46.85,80.075
NetL9_L1': L9.L1' U14.7 | length 3.3
  L1 - TOP w0.35: L9.L1'@52.05,80.075 52.875,79.25 U14.7@52.875,77.15
NetL9_L2': L9.L2' U14.6 | length 3.3
  L1 - TOP w0.35: U14.6@53.525,77.15 53.525,79.25 L9.L2'@54.35,80.075
NetL10_1: L10.1 U19.18 | length 2.2
  L1 - TOP w0.25: L10.1@25.6,30.3 25.7,30.4 26.1,30.4 26.65,30.95 U19.18@26.65,31.8
NetLD1_1: LD1.1 R125.2 | length 2.3
  L1 - TOP w0.5: LD1.1@55.6,3.6 R125.2@55.6,5.9
NetLD2_1: LD2.1 R126.2 | length 2.3
  L1 - TOP w0.5: LD2.1@73.2,3.6 R126.2@73.2,5.9
NetLD3_1: LD3.1 R127.2 | length 1.4
  L1 - TOP w0.5: LD3.1@36.46,3.61 R127.2@36.46,5
NetLD4_1: LD4.1 R128.2 | length 2.3
  L1 - TOP w0.5: LD4.1@54.06,3.61 R128.2@54.06,5.91
NetLD5_1: LD5.1 R138.2 | length 4.2
  L1 - TOP w0.165: LD5.1@26.8,46.005 27.15,46.005 28,45.155 28,43.255 R138.2@27.5,42.755
NetLD5_3: LD5.3 R152.2 | length 2.3
  L1 - TOP w0.5: LD5.3@29.8,44.505 30.25,44.505 30.9,45.155 R152.2@31.8,45.155
NetLD5_4: LD5.4 R137.2 | length 4.2
  L1 - TOP w0.165: R137.2@29,42.755 28.5,43.255 28.5,45.055 29.45,46.005 LD5.4@29.8,46.005
NetLD6_1: LD6.1 R218.1 | length 2
  L1 - TOP w0.165: LD6.1@23.55,17.05 R218.1@25.55,17.05
NetLD6_4: LD6.4 R219.1 | length 2
  L1 - TOP w0.165: R219.1@22.8,14.425 23.55,15.175 LD6.4@23.55,16.1
NetLD7_1: LD7.1 R246.2 | length 1.7
  L1 - TOP w0.2: LD7.1@85.8,30.35 R246.2@85.8,32.1
NetLD7_3: LD7.3 R244.2 | length 4.1
  L1 - TOP w0.2: R244.2@87.3,32.1 87.3,30 88.45,28.85 LD7.3@88.8,28.85
NetLD7_4: LD7.4 R245.2 | length 1.7
  L1 - TOP w0.2: LD7.4@88.8,30.35 R245.2@88.8,32.1
NetLD8_1: LD8.1 R257.1 | length 1.9
  L1 - TOP w0.14: LD8.1@120.775,7 120.775,5.575 R257.1@121.1,5.25
NetLD8_3: LD8.3 U32.15 | length 20.1
  L1 - TOP w0.2: LD8.3@119.825,8.8 119.825,11.425 v1(122,13.6) ; v1(125.6,24.7) 126.185,24.115 U32.15@127.12,24.115
  L6 - BOT w0.2: v1(122,13.6) 122,13.8 125.6,17.4 v1(125.6,24.7)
